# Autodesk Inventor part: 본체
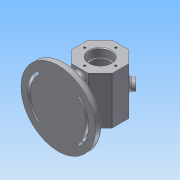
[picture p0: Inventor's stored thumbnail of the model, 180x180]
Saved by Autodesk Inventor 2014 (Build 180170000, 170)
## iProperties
Created: 2017-06
Part Number: 본체
Material: 알루미늄 6061
Document SubType Name: Modeling
Designer: NET
Density: 2.71 g/cm^3
Appearance: 알루미늄 - 평지
Mass: 594.804 g
Surface Area: 555.321 cm^2
Volume: 219.485 cm^3
Author: NET
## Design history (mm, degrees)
sketch "스케치1"
  geometry: L1 (30, 12.426)-(30, -12.426); L2 (30, -12.426)-(12.426, -30); L3 (12.426, -30)-(-12.426, -30); L4 (-12.426, -30)-(-30, -12.426); L5 (-30, -12.426)-(-30, 12.426); L6 (-30, 12.426)-(-12.426, 30); L7 (-12.426, 30)-(12.426, 30); L8 (12.426, 30)-(30, 12.426); L9 (0, 0)-(0, 64.888); L10 (0, 0)-(-12.426, 30); C1 r 30 at (0, 0); 2 further points
  constraints: 20 end point, 2 coincident, 1 centre point, 1 midpoint, 1 perpendicular, 1 tangent, 1 vertical, 1 vertical alignment, 17 other
  dimensions: "d0" = 60 diameter of C1
extrude "돌출1" new body sketch "스케치1" stored distance "d1" = 70; taper "d2" = 0 deg
node "작업 평면1"
sketch "스케치2"
  geometry: L1 (-81.172, 0)-(77.695, 0) reference; L2 (0, -77)-(0, 77) reference; C1 r 55 at (0, 0); 1 further point
  constraints: 1 centre point, 1 coincident
  dimensions: "d4" = 110 diameter of C1
extrude "돌출2" join sketch "스케치2" distance "d12" = 10; taper "d13" = 0 deg
sketch "스케치3"
  geometry: L1 (0, 0)-(30.406, 30.406); L2 (0, 0)-(30.406, -30.406); L3 (77, 0)-(-77, 0) reference; C1 r 55 at (0, 0) reference; A1 r 43 centre (0, 0) between (30.406, -30.406) and (30.406, 30.406); A2 r 45 centre (0, 0) between (31.82, -31.82) and (31.82, 31.82); A3 r 41 centre (0, 0) between (28.991, -28.991) and (28.991, 28.991); A4 r 2 centre (30.406, -30.406) between (28.991, -28.991) and (31.82, -31.82); A5 r 2 centre (30.406, 30.406) between (31.82, 31.82) and (28.991, 28.991)
  constraints: 10 point on circle, 5 centre point, 4 end point, 4 tangent, 1 coincident
  dimensions: "d14" = 2 radius of A4; "d16" = 86 diameter of A1; "d17" = 90 deg angle of L2 L1; "d18" = 45 deg angle of L1 L3
extrude "돌출3" cut sketch "스케치3" distance "d19" = 10; taper "d20" = 0 deg
sketch "스케치4"
  geometry: C1 r 55 at (0, 0) reference; A1 r 2 centre (30.406, 30.406) between (31.82, 31.82) and (28.991, 28.991) reference; A2 r 45 centre (0, 0) between (31.82, -31.82) and (31.82, 31.82) reference; A3 r 2 centre (30.406, -30.406) between (28.991, -28.991) and (31.82, -31.82) reference; A4 r 41 centre (0, 0) between (28.991, -28.991) and (28.991, 28.991) reference; A5 r 43 centre (0, 0) between (30.406, -30.406) and (30.406, 30.406); A6 r 48 centre (0, 0) between (33.941, -33.941) and (33.941, 33.941); A7 r 38 centre (0, 0) between (26.87, -26.87) and (26.87, 26.87); A8 r 5 centre (30.406, -30.406) between (26.87, -26.87) and (33.941, -33.941); A9 r 5 centre (30.406, 30.406) between (33.941, 33.941) and (26.87, 26.87)
  constraints: 10 point on circle, 5 centre point, 4 tangent, 1 coincident
  dimensions: "d21" = 5 radius of A9
extrude "돌출4" cut sketch "스케치4" distance "d22" = 3; taper "d23" = 0 deg
sketch "스케치5"
  geometry: L1 (0, 24)-(0, -24); L2 (-5, 24)-(-5, -24); L3 (5, -24)-(5, 24); C1 r 55 at (0, 0) reference; A1 r 5 centre (0, 24) between (5, 24) and (-5, 24); A2 r 5 centre (0, -24) between (-5, -24) and (5, -24)
  constraints: 8 end point, 4 point on circle, 4 tangent, 2 centre point, 1 midpoint, 1 parallel, 1 vertical
  dimensions: "d24" = 5 radius of A1; "d25" = 48 distance of L1.end L1.start
extrude "돌출5" join sketch "스케치5" stored distance "d26" = 3; taper "d27" = 0 deg
sketch "스케치6"
  geometry: L1 (16, 35)-(16, 23); L2 (16, 23)-(14, 23); L3 (14, 23)-(14, 20); L4 (14, 20)-(25, 20); L5 (25, 20)-(25, -20); L6 (25, -20)-(14, -20); L7 (14, -20)-(14, -23); L8 (14, -23)-(16, -23); L9 (16, -23)-(16, -35); L10 (16, -35)-(0, -35); L11 (0, -35)-(0, 35); L12 (0, 35)-(16, 35); L13 (-80.4, 0)-(48.4, 0) reference; L14 (12.426, -35)-(30, -35) reference; L15 (30, 35)-(12.426, 35) reference; L16 (12.426, 35)-(-12.426, 35) reference; L17 (-12.426, -35)-(12.426, -35) reference; 3 further points
  constraints: 24 end point, 9 parallel, 3 collinear, 2 midpoint, 1 horizontal alignment, 1 perpendicular, 1 vertical, 1 vertical alignment
  dimensions: "d28" = 32 diameter of L1 L11; "d29" = 28 diameter of L3 L11; "d30" = 32 diameter of L9 L11; "d31" = 28 diameter of L7 L11; "d32" = 50 diameter of L5 L11; "d33" = 12 distance of L1.start L1.end; "d34" = 12 distance of L8.end L9.end; "d35" = 40 distance of L4.end L5.end
revolve "회전1" sketch "스케치6" stored, may be unused: angle "d36" = 90 deg
chamfer "모따기1" distance "d37" = 1; stored, may be unused: second distance "d38" = 2, angle "d39" = 45 deg
fillet "모깎기1" dims "d40" = 3
sketch "스케치7"
  geometry: C1 r 17 at (0, 0) reference; 1 further point
  constraints: 1 vertical alignment
  dimensions: "d41" = 23 distance of point (0, 23) C1.centre
hole "구멍1" sketch "스케치7" at (0, 23) diameter "d42" = 3.242; stored, may be unused: countersink angle "d46" = 90 deg, drill point angle "d48" = 118 deg; dims "d43" = 8, "d44" = 4, "d45" = 2, "d47" = 10
sketch "스케치8" dims "d52" = 46
  geometry: C1 r 17 at (0, 0) reference; 2 further points
  constraints: 2 vertical alignment, 1 coincident, 2 other
hole "구멍2" sketch "스케치8" at (0, 23) diameter "d53" = 3.242; stored, may be unused: countersink angle "d57" = 90 deg, drill point angle "d59" = 118 deg; dims "d54" = 8, "d55" = 4, "d56" = 2, "d58" = 10
node "작업 평면2"
sketch "스케치10"
  geometry: C1 r 8 at (-12.426, 35); 1 further point
  constraints: 1 centre point, 1 coincident
  dimensions: "d64" = 16 diameter of C1
extrude "돌출6" join sketch "스케치10" stored distance "d65" = 3; taper "d66" = 0 deg
sketch "스케치11"
  geometry: C1 r 8 at (0, 0) reference; C2 r 4 at (0, 0)
  constraints: 1 centre point, 1 coincident
  dimensions: "d67" = 8 diameter of C2
extrude "돌출7" cut sketch "스케치11" distance "d68" = 16; taper "d69" = 0 deg
chamfer "모따기2" distance "d70" = 1; stored, may be unused: second distance "d71" = 2, angle "d72" = 45 deg
fillet "모깎기2" dims "d73" = 3
fillet "모깎기3" dims "d74" = 5
fillet "모깎기4" dims "d75" = 3
fillet "모깎기5" dims "d76" = 1
node "작업 평면3"
sketch "스케치13"
  geometry: L1 (24.024, 0)-(0, 0) reference; L2 (-17.988, 70)-(-17.988, 0) reference; 2 further points
  constraints: 1 other
  dimensions: "d78" = 35 distance from line of L1 point (12.012, 35); "d79" = 30 distance from line of L2 point (12.012, 35)
feature "엠보싱1" sketch "스케치13" dims "d0" = 60, "d80" = 0.5, "d81" = 0
fillet "모깎기6" dims "d82" = 0.3
node "솔리드1"
mirror "대칭1"
mirror "대칭2"
pattern_circular "원형 패턴1" dims angle "d50" = 360 deg
pattern_circular "원형 패턴2" dims angle "d61" = 360 deg
other parameters: "d3" = -62, "d63" = 7, "d77" = 4.5
